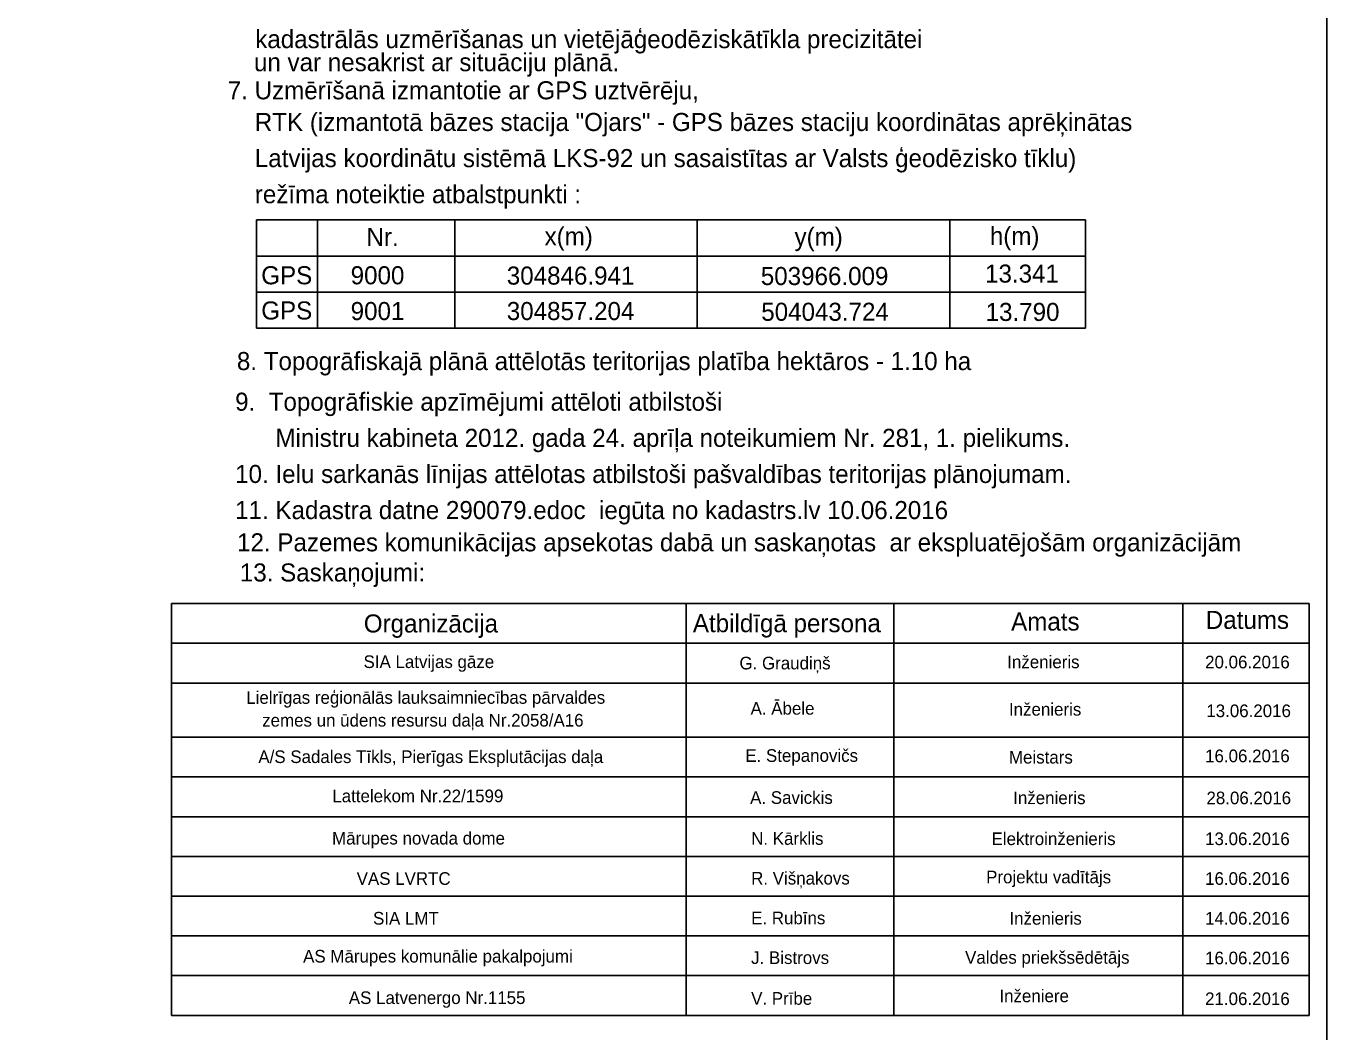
# Model space of a CAD drawing. Extents: x 503904 to 504094, y 304688 to 304960.
# Drawn here: x 504021.7 to 504093.7, y 304724 to 304779.7 of the extents above; entities that cross this region are included whole.
import ezdxf

# ---------------------------------------------------------------- set-up
doc = ezdxf.new("R2010")
doc.units = 0
doc.layers.add('RAMI_PLAN_####_TKST_#', color=7, linetype='Continuous')

msp = doc.modelspace()

# ---------------------------------------------------------------- linework, layer by layer
at = {"layer": 'RAMI_PLAN_####_TKST_#'}
for p, q in [((504034.424, 304762.995), (504034.424, 304768.995)), ((504080.327, 304768.995), (504034.424, 304768.995)), ((504037.804, 304762.995), (504037.804, 304768.995)), ((504045.408, 304762.995), (504045.408, 304768.995)), ((504058.827, 304762.995), (504058.827, 304768.995)), ((504072.827, 304762.995), (504072.827, 304768.995)), ((504080.327, 304762.995), (504080.327, 304768.995)), ((504080.327, 304766.995), (504034.424, 304766.995)), ((504080.327, 304764.995), (504034.424, 304764.995)), ((504080.327, 304762.995), (504034.424, 304762.995)), ((504029.722, 304747.753), (504029.722, 304724.953)), ((504092.722, 304747.753), (504029.722, 304747.753)), ((504058.217, 304747.753), (504058.217, 304724.953)), ((504069.722, 304747.753), (504069.722, 304724.953)), ((504085.722, 304747.753), (504085.722, 304724.953)), ((504092.722, 304747.753), (504092.722, 304724.953)), ((504092.722, 304745.553), (504029.722, 304745.553)), ((504092.722, 304743.353), (504029.722, 304743.353)), ((504092.722, 304740.353), (504029.722, 304740.353)), ((504092.722, 304738.153), (504029.722, 304738.153)), ((504092.722, 304735.953), (504029.722, 304735.953)), ((504092.722, 304733.753), (504029.722, 304733.753)), ((504092.722, 304731.553), (504029.722, 304731.553)), ((504092.722, 304729.353), (504029.722, 304729.353)), ((504092.722, 304727.153), (504029.722, 304727.153)), ((504092.722, 304724.953), (504029.722, 304724.953))]:
    msp.add_line(p, q, dxfattribs=at)
msp.add_lwpolyline([(503904.204, 304823.741), (504093.703, 304823.741), (504093.703, 304687.633), (503904.204, 304687.633)], close=True, dxfattribs=at)

# ---------------------------------------------------------------- texts
for s, height, rotation, p in [('    kadastrālās uzmērīšanas un vietējāģeodēziskātīkla precizitātei ', 1, 360, (504032.872, 304778.51)), ('    un var nesakrist ar situāciju plānā.', 1, 360, (504032.802, 304777.232)), ('7. Uzmērīšanā izmantotie ar GPS uztvērēju,', 1, 360, (504032.837, 304775.677)), ('Nr.', 1, 360, (504040.519, 304767.554)), ('x(m)', 1, 360, (504050.379, 304767.59)), ('y(m)', 1, 360, (504064.22, 304767.566)), ('h(m)', 1, 360, (504075.035, 304767.611)), ('GPS', 1, 360, (504034.69, 304765.433)), ('9000', 1, 360, (504039.642, 304765.433)), ('304846.941', 1, 360, (504048.287, 304765.415)), ('503966.009', 1, 360, (504062.353, 304765.391)), ('13.341', 1, 360, (504074.77, 304765.526)), ('GPS', 1, 360, (504034.69, 304763.484)), ('9001', 1, 360, (504039.642, 304763.452)), ('304857.204', 1, 360, (504048.287, 304763.452)), ('504043.724', 1, 360, (504062.377, 304763.412)), ('13.790', 1, 360, (504074.802, 304763.404)), ('8. Topogrāfiskajā plānā attēlotās teritorijas platība hektāros - 1.10 ha', 1, 360, (504033.341, 304760.682)), ('9.  Topogrāfiskie apzīmējumi attēloti atbilstoši ', 1, 360, (504033.245, 304758.431)), ('      Ministru kabineta 2012. gada 24. aprīļa noteikumiem Nr. 281, 1. pielikums.', 1, 360, (504033.245, 304756.431)), ('10. Ielu sarkanās līnijas attēlotas atbilstoši pašvaldības teritorijas plānojumam.', 1, 360, (504033.245, 304754.431)), ('11. Kadastra datne 290079.edoc  iegūta no kadastrs.lv 10.06.2016', 1, 360, (504033.245, 304752.431)), ('12. Pazemes komunikācijas apsekotas dabā un saskaņotas  ar ekspluatējošām organizācijām', 1, 360, (504033.353, 304750.646)), ('13. Saskaņojumi:', 1, 360, (504033.505, 304748.977)), ('Organizācija', 1, 360, (504040.37, 304746.153)), ('Atbildīgā persona', 1, 360, (504058.591, 304746.169)), ('Amats', 1, 360, (504076.213, 304746.26)), ('Datums', 1, 360, (504086.995, 304746.351)), ('SIA Latvijas gāze', 0.7, 360, (504040.356, 304744.185)), ('G. Graudiņš', 0.7, 360, (504061.17, 304744.109)), ('Inženieris', 0.7, 360, (504075.998, 304744.174)), ('20.06.2016', 0.7, 360, (504086.955, 304744.166)), ('Lielrīgas reģionālās lauksaimniecības pārvaldes', 0.7, 0.01325, (504033.861, 304742.201)), ('A. Ābele', 0.7, 360, (504061.786, 304741.603)), ('Inženieris', 0.7, 360, (504076.093, 304741.55)), ('13.06.2016', 0.7, 360, (504087.022, 304741.466)), ('zemes un ūdens resursu daļa Nr.2058/A16', 0.7, 0.01325, (504034.742, 304740.941)), ('E. Stepanovičs', 0.7, 360, (504061.494, 304738.989)), ('A/S Sadales Tīkls, Pierīgas Eksplutācijas daļa', 0.7, 360, (504034.532, 304738.924)), ('Meistars', 0.7, 360, (504076.093, 304738.896)), ('16.06.2016', 0.7, 360, (504086.955, 304738.968)), ('Lattelekom Nr.22/1599', 0.7, 360, (504038.627, 304736.752)), ('A. Savickis', 0.7, 360, (504061.761, 304736.662)), ('Inženieris', 0.7, 360, (504076.328, 304736.647)), ('28.06.2016', 0.7, 360, (504087.03, 304736.641)), ('Mārupes novada dome', 0.7, 360, (504038.612, 304734.412)), ('N. Kārklis', 0.7, 360, (504061.817, 304734.396)), ('Elektroinženieris', 0.7, 360, (504075.13, 304734.381)), ('13.06.2016', 0.7, 360, (504086.955, 304734.379)), ('VAS LVRTC', 0.7, 360, (504039.975, 304732.178)), ('R. Višņakovs', 0.7, 360, (504061.817, 304732.196)), ('Projektu vadītājs', 0.7, 360, (504074.829, 304732.263)), ('16.06.2016', 0.7, 360, (504086.955, 304732.179)), ('SIA LMT', 0.7, 360, (504040.881, 304729.978)), ('E. Rubīns', 0.7, 360, (504061.817, 304729.996)), ('Inženieris', 0.7, 360, (504076.12, 304729.973)), ('14.06.2016', 0.7, 360, (504086.955, 304729.979)), ('AS Mārupes komunālie pakalpojumi', 0.7, 360, (504037.009, 304727.877)), ('J. Bistrovs', 0.7, 360, (504061.817, 304727.796)), ('Valdes priekšsēdētājs', 0.7, 360, (504073.664, 304727.811)), ('16.06.2016', 0.7, 360, (504086.955, 304727.779)), ('AS Latvenergo Nr.1155', 0.7, 360, (504039.539, 304725.58)), ('V. Prībe', 0.7, 360, (504061.817, 304725.539)), ('Inženiere', 0.7, 360, (504075.563, 304725.68)), ('21.06.2016', 0.7, 360, (504086.955, 304725.523))]:
    msp.add_text(s, height=height, rotation=rotation, dxfattribs=at).set_placement(p)
for s, p in [('  RTK (izmantotā bāzes stacija "Ojars" - GPS bāzes staciju koordinātas aprēķinātas ', (504033.592, 304773.921)), ('  Latvijas koordinātu sistēmā LKS-92 un sasaistītas ar Valsts ģeodēzisko tīklu) ', (504033.592, 304771.921)), ('  režīma noteiktie atbalstpunkti :', (504033.592, 304769.921))]:
    msp.add_text(s, height=1, dxfattribs=at).set_placement(p)

doc.saveas('drawing.dxf')
